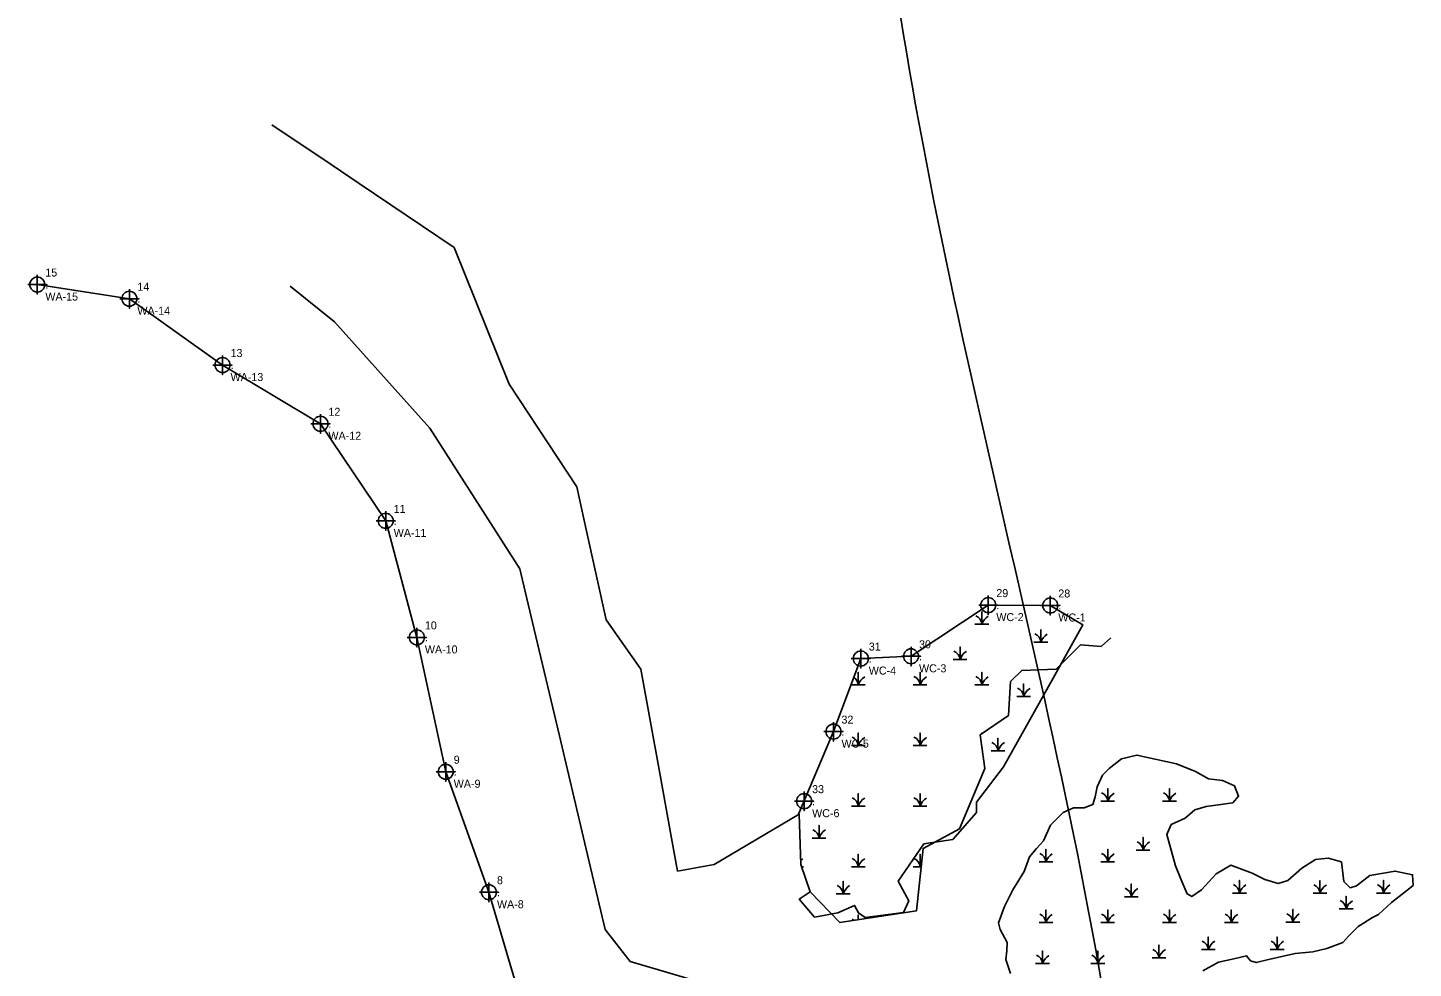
# Model space of a CAD drawing. Extents: x 1835303 to 1835785, y 366400 to 367935.
# Drawn here: x 1835352.5 to 1835785.5, y 367166.6 to 367460.4 of the extents above; entities that cross this region are included whole.
import ezdxf

# ---------------------------------------------------------------- set-up
doc = ezdxf.new("R2010")
doc.units = 0
for name, color, linetype in [('Default', 7, 'Continuous'), ('Exist Environmental Wetland Boundary', 7, 'Continuous'), ('Exist Environmental Wetland Boundary Cogo Comment', 7, 'Continuous'), ('Exist Environmental Wetland Boundary Cogo Elevation', 7, 'Continuous'), ('Exist Environmental Wetland Boundary Cogo Number', 7, 'Continuous'), ('Exist Environmental Wetland Boundary Cogo Point CELL', 7, 'Continuous'), ('Exist Hydro Jurisdictional Stream or Body of Water NEU Mitigable', 7, 'Continuous'), ('Exist Hydro Swamp or Marsh', 7, 'Continuous')]:
    doc.layers.add(name, color=color, linetype=linetype)

msp = doc.modelspace()

# ---------------------------------------------------------------- linework, layer by layer
at = {"layer": 'Default'}
msp.add_spline([(1835622.69, 367917.35), (1835610.42, 367781.31), (1835628.86, 367442.44), (1835700.95, 367057.13), (1835601.57, 366602.08), (1835470.17, 366400.05)], degree=3, dxfattribs=at)
at = {"layer": 'Exist Environmental Wetland Boundary'}
for points in [[(1835672.04, 367279.91), (1835652.67, 367280.03), (1835628.52, 367264.03), (1835612.82, 367263.33), (1835604.29, 367240.5), (1835593.38, 367214.67)], [(1835593.52, 367214.75), (1835594.13, 367198.99), (1835596.97, 367190.39), (1835593.59, 367188.19), (1835598.38, 367182.54), (1835605.61, 367183.84), (1835610.86, 367186.2), (1835612.09, 367183.86), (1835614.19, 367182.42), (1835626.17, 367184), (1835627.79, 367187.59), (1835624.51, 367193.79), (1835632.52, 367205.43), (1835641.57, 367206.8), (1835649.02, 367215.26), (1835649.02, 367218.44), (1835657.42, 367229.52), (1835672.95, 367257.25), (1835682.22, 367273.84), (1835672.04, 367279.91)], [(1835699.08, 367233.16), (1835694.3, 367231.99), (1835690.47, 367229), (1835688.35, 367226.86), (1835686.69, 367223.26), (1835686.1, 367220.17), (1835685.36, 367217.7), (1835682.62, 367216.64), (1835679.28, 367216.65), (1835679.28, 367216.65), (1835676.1, 367215.22), (1835672.08, 367211.23), (1835669.9, 367206.36), (1835667.75, 367204.03)], [(1835694.3, 367231.99), (1835699.08, 367233.16), (1835711.51, 367230.48), (1835717.37, 367228.01), (1835721.52, 367225.79), (1835725.83, 367225.19), (1835729.63, 367223.52), (1835730.85, 367220.36), (1835729.04, 367218.3), (1835720.71, 367217.15), (1835717.16, 367216.06), (1835714.18, 367213.49), (1835709.84, 367211.46), (1835708.43, 367208.35), (1835711.17, 367198.56), (1835712.89, 367194.14), (1835714.81, 367189.8), (1835716.26, 367188.95), (1835719.3, 367191.1), (1835723.92, 367196.05), (1835728.43, 367198.77), (1835728.43, 367198.77), (1835735.1, 367196.32), (1835739.08, 367194.33), (1835743.22, 367193.03), (1835746.25, 367193.97), (1835750.66, 367197.81), (1835754.88, 367200.57), (1835758.87, 367201.01), (1835763.02, 367199.81), (1835763.77, 367193.65), (1835765.72, 367191.74), (1835767.7, 367192.27), (1835771.86, 367195.53), (1835779.8, 367196.92), (1835785.27, 367195.8), (1835785.47, 367192.44), (1835781.97, 367189.72), (1835778.68, 367187.09), (1835774.57, 367183.31), (1835772.77, 367182.46), (1835768.24, 367179.64), (1835765.33, 367176.66), (1835763.41, 367174.61), (1835758.47, 367172.74), (1835754.11, 367171.73), (1835748.52, 367171.18)], [(1835659.64, 367164.93), (1835658.19, 367169.3), (1835658.48, 367171.98), (1835658.55, 367174.58), (1835656.37, 367178.72), (1835655.88, 367180.78), (1835657.72, 367185.91), (1835660.37, 367191.05), (1835663.88, 367196.8), (1835665.56, 367201.35), (1835667.75, 367204.03)], [(1835748.52, 367171.18), (1835739.78, 367169.19), (1835736.38, 367168.34), (1835734.64, 367168.92), (1835733.39, 367170.46), (1835729.37, 367169.47), (1835724.65, 367168.46), (1835719.75, 367165.76)]]:
    msp.add_lwpolyline(points, dxfattribs=at)
at = {"layer": 'Exist Environmental Wetland Boundary Cogo Point CELL'}
for points in [[(1835355.5, 367383.19), (1835355.5, 367377.19), (1835355.5, 367380.19), (1835358.5, 367380.19), (1835352.5, 367380.19)], [(1835384.27, 367378.76), (1835384.27, 367372.76), (1835384.27, 367375.76), (1835387.27, 367375.76), (1835381.27, 367375.76)], [(1835413.38, 367358.04), (1835413.38, 367352.04), (1835413.38, 367355.04), (1835416.38, 367355.04), (1835410.38, 367355.04)], [(1835443.97, 367339.69), (1835443.97, 367333.69), (1835443.97, 367336.69), (1835446.97, 367336.69), (1835440.97, 367336.69)], [(1835464.36, 367309.36), (1835464.36, 367303.36), (1835464.36, 367306.36), (1835467.36, 367306.36), (1835461.36, 367306.36)], [(1835652.67, 367283.03), (1835652.67, 367277.03), (1835652.67, 367280.03), (1835655.67, 367280.03), (1835649.67, 367280.03)], [(1835672.04, 367282.91), (1835672.04, 367276.91), (1835672.04, 367279.91), (1835675.04, 367279.91), (1835669.04, 367279.91)], [(1835474.1, 367272.94), (1835474.1, 367266.94), (1835474.1, 367269.94), (1835477.1, 367269.94), (1835471.1, 367269.94)], [(1835612.82, 367266.33), (1835612.82, 367260.33), (1835612.82, 367263.33), (1835615.82, 367263.33), (1835609.82, 367263.33)], [(1835628.52, 367267.03), (1835628.52, 367261.03), (1835628.52, 367264.03), (1835631.52, 367264.03), (1835625.52, 367264.03)], [(1835604.29, 367243.5), (1835604.29, 367237.5), (1835604.29, 367240.5), (1835607.29, 367240.5), (1835601.29, 367240.5)], [(1835483.12, 367230.96), (1835483.12, 367224.96), (1835483.12, 367227.96), (1835486.12, 367227.96), (1835480.12, 367227.96)], [(1835595.11, 367221.77), (1835595.11, 367215.77), (1835595.11, 367218.77), (1835598.11, 367218.77), (1835592.11, 367218.77)], [(1835496.63, 367193.31), (1835496.63, 367187.31), (1835496.63, 367190.31), (1835499.63, 367190.31), (1835493.63, 367190.31)]]:
    msp.add_lwpolyline(points, dxfattribs=at)
for centre in [(1835355.5, 367380.19), (1835384.27, 367375.76), (1835413.38, 367355.04), (1835443.97, 367336.69), (1835464.36, 367306.36), (1835652.67, 367280.03), (1835672.04, 367279.91), (1835474.1, 367269.94), (1835612.82, 367263.33), (1835628.52, 367264.03), (1835604.29, 367240.5), (1835483.12, 367227.96), (1835595.11, 367218.77), (1835496.63, 367190.31)]:
    msp.add_circle(centre, 2.34, dxfattribs=at)
at = {"layer": 'Exist Hydro Jurisdictional Stream or Body of Water NEU Mitigable'}
for points in [[(1835566.95, 367198.99), (1835555.56, 367196.92), (1835553.49, 367208.31), (1835550.11, 367226.91), (1835544.08, 367260.05), (1835533.21, 367275.41), (1835527.02, 367303.64), (1835524.09, 367316.98), (1835502.92, 367349.08), (1835485.71, 367391.76), (1835456.11, 367411.73), (1835444.39, 367419.63), (1835432.66, 367427.54), (1835428.8, 367430.14)], [(1835452.88, 366882.76), (1835503.69, 366919.31), (1835518.49, 366962.01), (1835520.69, 367005.91), (1835520.98, 367049.5), (1835516.67, 367090.93), (1835510.8, 367142.28), (1835496.63, 367190.31), (1835483.12, 367227.96), (1835474.1, 367269.94), (1835464.36, 367306.36), (1835443.97, 367336.69), (1835413.38, 367355.04), (1835384.27, 367375.76), (1835355.5, 367380.19)], [(1835573.83, 367161.12), (1835566.61, 367161.12), (1835540.79, 367168.7), (1835532.97, 367178.64), (1835527.02, 367203.81), (1835518.65, 367239.18), (1835510.27, 367274.56), (1835506.3, 367291.35), (1835478.11, 367335.29), (1835448.35, 367368.55), (1835434.53, 367379.65)], [(1835566.95, 367198.99), (1835593.52, 367214.75), (1835594.13, 367198.99), (1835596.97, 367190.39), (1835606.31, 367180.85), (1835630.26, 367184.51), (1835632.29, 367203.99), (1835643.66, 367210.08), (1835651.57, 367228.96), (1835650.15, 367239.52), (1835658.95, 367245.52), (1835659.57, 367256.15), (1835663.14, 367259.61), (1835673.9, 367260.02), (1835681.51, 367267.63), (1835687.91, 367267.12), (1835690.95, 367269.76)]]:
    msp.add_lwpolyline(points, dxfattribs=at)
at = {"layer": 'Exist Hydro Swamp or Marsh'}
for p, q in [((1835669.09, 367270.19), (1835669.09, 367270.19)), ((1835643.83, 367264.8), (1835643.83, 367264.8)), ((1835663.7, 367253.24), (1835663.7, 367253.24)), ((1835655.69, 367236.29), (1835655.69, 367236.29)), ((1835599.77, 367209.02), (1835599.77, 367209.02)), ((1835701.03, 367205.27), (1835701.03, 367205.27)), ((1835607.32, 367191.6), (1835607.32, 367191.6)), ((1835697.35, 367190.7), (1835697.35, 367190.7)), ((1835731.16, 367191.85), (1835731.16, 367191.85)), ((1835756.3, 367191.79), (1835756.3, 367191.79)), ((1835776.17, 367191.85), (1835776.17, 367191.85)), ((1835764.49, 367186.88), (1835764.49, 367186.88)), ((1835747.84, 367182.79), (1835747.84, 367182.79)), ((1835721.42, 367174.21), (1835721.42, 367174.21)), ((1835742.92, 367174.21), (1835742.92, 367174.21)), ((1835669.61, 367169.8), (1835669.61, 367169.8)), ((1835686.88, 367169.8), (1835686.88, 367169.8)), ((1835705.99, 367171.64), (1835705.99, 367171.64))]:
    msp.add_line(p, q, dxfattribs=at)
for points in [[(1835648.5, 367274.04), (1835650.65, 367274.04), (1835650.65, 367277.98), (1835650.65, 367274.04), (1835652.8, 367274.04)], [(1835666.94, 367268.41), (1835669.1, 367268.41), (1835669.1, 367272.35), (1835669.1, 367268.41), (1835671.25, 367268.41)], [(1835641.68, 367263.01), (1835643.83, 367263.01), (1835643.83, 367266.96), (1835643.83, 367263.01), (1835645.98, 367263.01)], [(1835609.88, 367255.09), (1835612.03, 367255.09), (1835612.03, 367259.03), (1835612.03, 367255.09), (1835614.18, 367255.09)], [(1835629.19, 367255.09), (1835631.34, 367255.09), (1835631.34, 367259.03), (1835631.34, 367255.09), (1835633.49, 367255.09)], [(1835648.5, 367255.09), (1835650.65, 367255.09), (1835650.65, 367259.03), (1835650.65, 367255.09), (1835652.8, 367255.09)], [(1835661.55, 367251.46), (1835663.7, 367251.46), (1835663.7, 367255.4), (1835663.7, 367251.46), (1835665.85, 367251.46)], [(1835609.88, 367236.14), (1835612.03, 367236.14), (1835612.03, 367240.08), (1835612.03, 367236.14), (1835614.18, 367236.14)], [(1835629.19, 367236.14), (1835631.34, 367236.14), (1835631.34, 367240.08), (1835631.34, 367236.14), (1835633.49, 367236.14)], [(1835650.65, 367239.86), (1835650.65, 367240.08), (1835650.65, 367239.86)], [(1835653.54, 367234.51), (1835655.69, 367234.51), (1835655.69, 367238.45), (1835655.69, 367234.51), (1835657.84, 367234.51)], [(1835609.88, 367217.19), (1835612.03, 367217.19), (1835612.03, 367221.13), (1835612.03, 367217.19), (1835614.18, 367217.19)], [(1835629.19, 367217.19), (1835631.34, 367217.19), (1835631.34, 367221.13), (1835631.34, 367217.19), (1835633.49, 367217.19)], [(1835687.82, 367218.74), (1835689.98, 367218.74), (1835689.98, 367222.68), (1835689.98, 367218.74), (1835692.13, 367218.74)], [(1835707.14, 367218.74), (1835709.29, 367218.74), (1835709.29, 367222.68), (1835709.29, 367218.74), (1835711.44, 367218.74)], [(1835597.62, 367207.23), (1835599.77, 367207.23), (1835599.77, 367211.18), (1835599.77, 367207.23), (1835601.92, 367207.23)], [(1835668.51, 367199.79), (1835670.66, 367199.79), (1835670.66, 367203.73), (1835670.66, 367199.79), (1835672.81, 367199.79)], [(1835687.82, 367199.79), (1835689.98, 367199.79), (1835689.98, 367203.73), (1835689.98, 367199.79), (1835692.13, 367199.79)], [(1835698.88, 367203.48), (1835701.03, 367203.48), (1835701.03, 367207.43), (1835701.03, 367203.48), (1835703.18, 367203.48)], [(1835609.88, 367198.24), (1835612.03, 367198.24), (1835612.03, 367202.18), (1835612.03, 367198.24), (1835614.18, 367198.24)], [(1835629.19, 367198.24), (1835631.34, 367198.24), (1835631.34, 367202.18), (1835631.34, 367198.24), (1835631.69, 367198.24)], [(1835594.37, 367198.24), (1835594.87, 367198.24)], [(1835605.17, 367189.82), (1835607.32, 367189.82), (1835607.32, 367193.77), (1835607.32, 367189.82), (1835609.47, 367189.82)], [(1835695.2, 367188.92), (1835697.35, 367188.92), (1835697.35, 367192.86), (1835697.35, 367188.92), (1835699.5, 367188.92)], [(1835729.01, 367190.07), (1835731.16, 367190.07), (1835731.16, 367194.01), (1835731.16, 367190.07), (1835733.31, 367190.07)], [(1835754.15, 367190.01), (1835756.3, 367190.01), (1835756.3, 367193.96), (1835756.3, 367190.01), (1835758.45, 367190.01)], [(1835774.02, 367190.07), (1835776.17, 367190.07), (1835776.17, 367194.01), (1835776.17, 367190.07), (1835778.32, 367190.07)], [(1835762.34, 367185.1), (1835764.49, 367185.1), (1835764.49, 367189.04), (1835764.49, 367185.1), (1835766.64, 367185.1)], [(1835612.03, 367181.73), (1835612.03, 367183.23), (1835612.03, 367181.73)], [(1835668.51, 367180.84), (1835670.66, 367180.84), (1835670.66, 367184.78), (1835670.66, 367180.84), (1835672.81, 367180.84)], [(1835687.82, 367180.84), (1835689.98, 367180.84), (1835689.98, 367184.78), (1835689.98, 367180.84), (1835692.13, 367180.84)], [(1835707.14, 367180.84), (1835709.29, 367180.84), (1835709.29, 367184.78), (1835709.29, 367180.84), (1835711.44, 367180.84)], [(1835726.45, 367180.84), (1835728.6, 367180.84), (1835728.6, 367184.78), (1835728.6, 367180.84), (1835730.75, 367180.84)], [(1835745.69, 367181), (1835747.84, 367181), (1835747.84, 367184.95), (1835747.84, 367181), (1835749.99, 367181)], [(1835703.84, 367169.85), (1835705.99, 367169.85), (1835705.99, 367173.8), (1835705.99, 367169.85), (1835708.14, 367169.85)], [(1835719.27, 367172.43), (1835721.42, 367172.43), (1835721.42, 367176.37), (1835721.42, 367172.43), (1835723.57, 367172.43)], [(1835740.77, 367172.43), (1835742.92, 367172.43), (1835742.92, 367176.37), (1835742.92, 367172.43), (1835745.07, 367172.43)], [(1835667.46, 367168.02), (1835669.61, 367168.02), (1835669.61, 367171.96), (1835669.61, 367168.02), (1835671.76, 367168.02)], [(1835684.73, 367168.02), (1835686.88, 367168.02), (1835686.88, 367171.96), (1835686.88, 367168.02), (1835689.03, 367168.02)]]:
    msp.add_lwpolyline(points, dxfattribs=at)
for centre, radius, start, end in [((1835647.59, 367273.82), 3.07, 4.1403, 67.535), ((1835655.21, 367272.52), 4.81, 122.1274, 161.6222), ((1835666.03, 367268.19), 3.07, 4.1403, 67.535), ((1835673.66, 367266.89), 4.81, 122.1274, 161.6222), ((1835640.76, 367262.79), 3.07, 4.1403, 67.535), ((1835648.39, 367261.5), 4.81, 122.1274, 161.6222), ((1835608.96, 367254.87), 3.07, 4.1403, 57.2963), ((1835616.59, 367253.57), 4.81, 122.1274, 161.6222), ((1835628.27, 367254.87), 3.07, 4.1403, 67.535), ((1835635.9, 367253.57), 4.81, 122.1274, 161.6222), ((1835647.59, 367254.87), 3.07, 4.1403, 67.535), ((1835655.21, 367253.57), 4.81, 122.1274, 161.6222), ((1835660.64, 367251.24), 3.07, 4.1403, 67.535), ((1835668.26, 367249.94), 4.81, 122.1274, 161.6222), ((1835608.96, 367235.92), 3.07, 4.1403, 67.535), ((1835616.59, 367234.62), 4.81, 122.1274, 161.6222), ((1835628.27, 367235.92), 3.07, 4.1403, 67.535), ((1835635.9, 367234.62), 4.81, 122.1274, 161.6222), ((1835652.63, 367234.29), 3.07, 4.1403, 67.535), ((1835660.25, 367232.99), 4.81, 122.1274, 161.6222), ((1835686.91, 367218.52), 3.07, 4.1403, 67.535), ((1835694.54, 367217.22), 4.81, 122.1274, 161.6222), ((1835706.22, 367218.52), 3.07, 4.1403, 67.535), ((1835713.85, 367217.22), 4.81, 122.1274, 161.6222), ((1835608.96, 367216.97), 3.07, 4.1403, 67.535), ((1835616.59, 367215.67), 4.81, 122.1274, 161.6222), ((1835628.27, 367216.97), 3.07, 4.1403, 67.535), ((1835635.9, 367215.67), 4.81, 122.1274, 161.6222), ((1835596.7, 367207.01), 3.07, 4.1403, 67.535), ((1835604.33, 367205.72), 4.81, 122.1274, 161.6222), ((1835697.96, 367203.26), 3.07, 4.1403, 67.535), ((1835705.59, 367201.97), 4.81, 122.1274, 161.6222), ((1835597.28, 367196.72), 4.81, 122.1274, 131.779), ((1835608.96, 367198.02), 3.07, 4.1403, 67.535), ((1835616.59, 367196.72), 4.81, 122.1274, 161.6222), ((1835628.27, 367198.02), 3.07, 4.1403, 67.535), ((1835635.9, 367196.72), 4.81, 148.8333, 161.6222), ((1835667.6, 367199.57), 3.07, 4.1403, 67.535), ((1835675.22, 367198.27), 4.81, 122.1274, 161.6222), ((1835686.91, 367199.57), 3.07, 4.1403, 67.535), ((1835694.54, 367198.27), 4.81, 122.1274, 161.6222), ((1835604.25, 367189.6), 3.07, 4.1403, 67.535), ((1835611.88, 367188.3), 4.81, 122.1274, 161.6222), ((1835694.28, 367188.7), 3.07, 4.1403, 67.535), ((1835701.91, 367187.4), 4.81, 122.1274, 161.6222), ((1835728.09, 367189.85), 3.07, 4.1403, 67.535), ((1835735.72, 367188.55), 4.81, 122.1274, 161.6222), ((1835753.23, 367189.79), 3.07, 4.1403, 67.535), ((1835760.86, 367188.5), 4.81, 122.1274, 161.6222), ((1835773.11, 367189.85), 3.07, 4.1403, 67.535), ((1835780.73, 367188.55), 4.81, 122.1274, 161.6222), ((1835761.42, 367184.88), 3.07, 4.1403, 67.535), ((1835769.05, 367183.58), 4.81, 122.1274, 161.6222), ((1835608.96, 367179.07), 3.07, 53.4792, 67.535), ((1835667.6, 367180.62), 3.07, 4.1403, 67.535), ((1835675.22, 367179.32), 4.81, 122.1274, 161.6222), ((1835686.91, 367180.62), 3.07, 4.1403, 67.535), ((1835694.54, 367179.32), 4.81, 122.1274, 161.6222), ((1835706.22, 367180.62), 3.07, 4.1403, 67.535), ((1835713.85, 367179.32), 4.81, 122.1274, 161.6222), ((1835725.53, 367180.62), 3.07, 4.1403, 67.535), ((1835733.16, 367179.32), 4.81, 122.1274, 161.6222), ((1835744.77, 367180.78), 3.07, 4.1403, 67.535), ((1835752.4, 367179.49), 4.81, 122.1274, 161.6222), ((1835718.35, 367172.2), 3.07, 4.1403, 67.535), ((1835725.98, 367170.91), 4.81, 122.1274, 161.6222), ((1835739.85, 367172.2), 3.07, 4.1403, 67.535), ((1835747.48, 367170.91), 4.81, 122.1274, 161.6222), ((1835666.54, 367167.79), 3.07, 4.1403, 67.535), ((1835674.17, 367166.5), 4.81, 122.1274, 161.6222), ((1835683.81, 367167.79), 3.07, 4.1403, 67.535), ((1835691.44, 367166.5), 4.81, 122.1274, 161.6222), ((1835702.92, 367169.63), 3.07, 4.1403, 67.535), ((1835710.55, 367168.34), 4.81, 122.1274, 161.6222)]:
    msp.add_arc(centre, radius, start, end, dxfattribs=at)

# ---------------------------------------------------------------- texts
at = {"layer": 'Exist Environmental Wetland Boundary Cogo Comment'}
for s, p in [('WA-15', (1835358, 367375.19)), ('WA-14', (1835386.77, 367370.76)), ('WA-13', (1835415.88, 367350.04)), ('WA-12', (1835446.47, 367331.69)), ('WA-11', (1835466.86, 367301.36)), ('WC-2', (1835655.17, 367275.03)), ('WC-1', (1835674.54, 367274.91)), ('WA-10', (1835476.6, 367264.94)), ('WC-4', (1835615.32, 367258.33)), ('WC-3', (1835631.02, 367259.03)), ('WC-5', (1835606.79, 367235.5)), ('WA-9', (1835485.62, 367222.97)), ('WC-6', (1835597.61, 367213.77)), ('WA-8', (1835499.13, 367185.32))]:
    msp.add_text(s, height=2.5, dxfattribs=at).set_placement(p)
at = {"layer": 'Exist Environmental Wetland Boundary Cogo Elevation'}
for p in [(1835358, 367378.94), (1835386.77, 367374.51), (1835415.88, 367353.79), (1835446.47, 367335.44), (1835466.86, 367305.11), (1835655.17, 367278.78), (1835674.54, 367278.66), (1835476.6, 367268.69), (1835615.32, 367262.08), (1835631.02, 367262.78), (1835606.79, 367239.25), (1835485.62, 367226.72), (1835597.61, 367217.52), (1835499.13, 367189.07)]:
    msp.add_text('.', height=2.5, dxfattribs=at).set_placement(p)
at = {"layer": 'Exist Environmental Wetland Boundary Cogo Number'}
for s, p in [('15', (1835358, 367382.69)), ('14', (1835386.77, 367378.26)), ('13', (1835415.88, 367357.54)), ('12', (1835446.47, 367339.19)), ('11', (1835466.86, 367308.86)), ('29', (1835655.17, 367282.53)), ('28', (1835674.54, 367282.41)), ('10', (1835476.6, 367272.44)), ('31', (1835615.32, 367265.83)), ('30', (1835631.02, 367266.53)), ('32', (1835606.79, 367243)), ('9', (1835485.62, 367230.47)), ('33', (1835597.61, 367221.27)), ('8', (1835499.13, 367192.82))]:
    msp.add_text(s, height=2.5, dxfattribs=at).set_placement(p)

doc.saveas('drawing.dxf')
